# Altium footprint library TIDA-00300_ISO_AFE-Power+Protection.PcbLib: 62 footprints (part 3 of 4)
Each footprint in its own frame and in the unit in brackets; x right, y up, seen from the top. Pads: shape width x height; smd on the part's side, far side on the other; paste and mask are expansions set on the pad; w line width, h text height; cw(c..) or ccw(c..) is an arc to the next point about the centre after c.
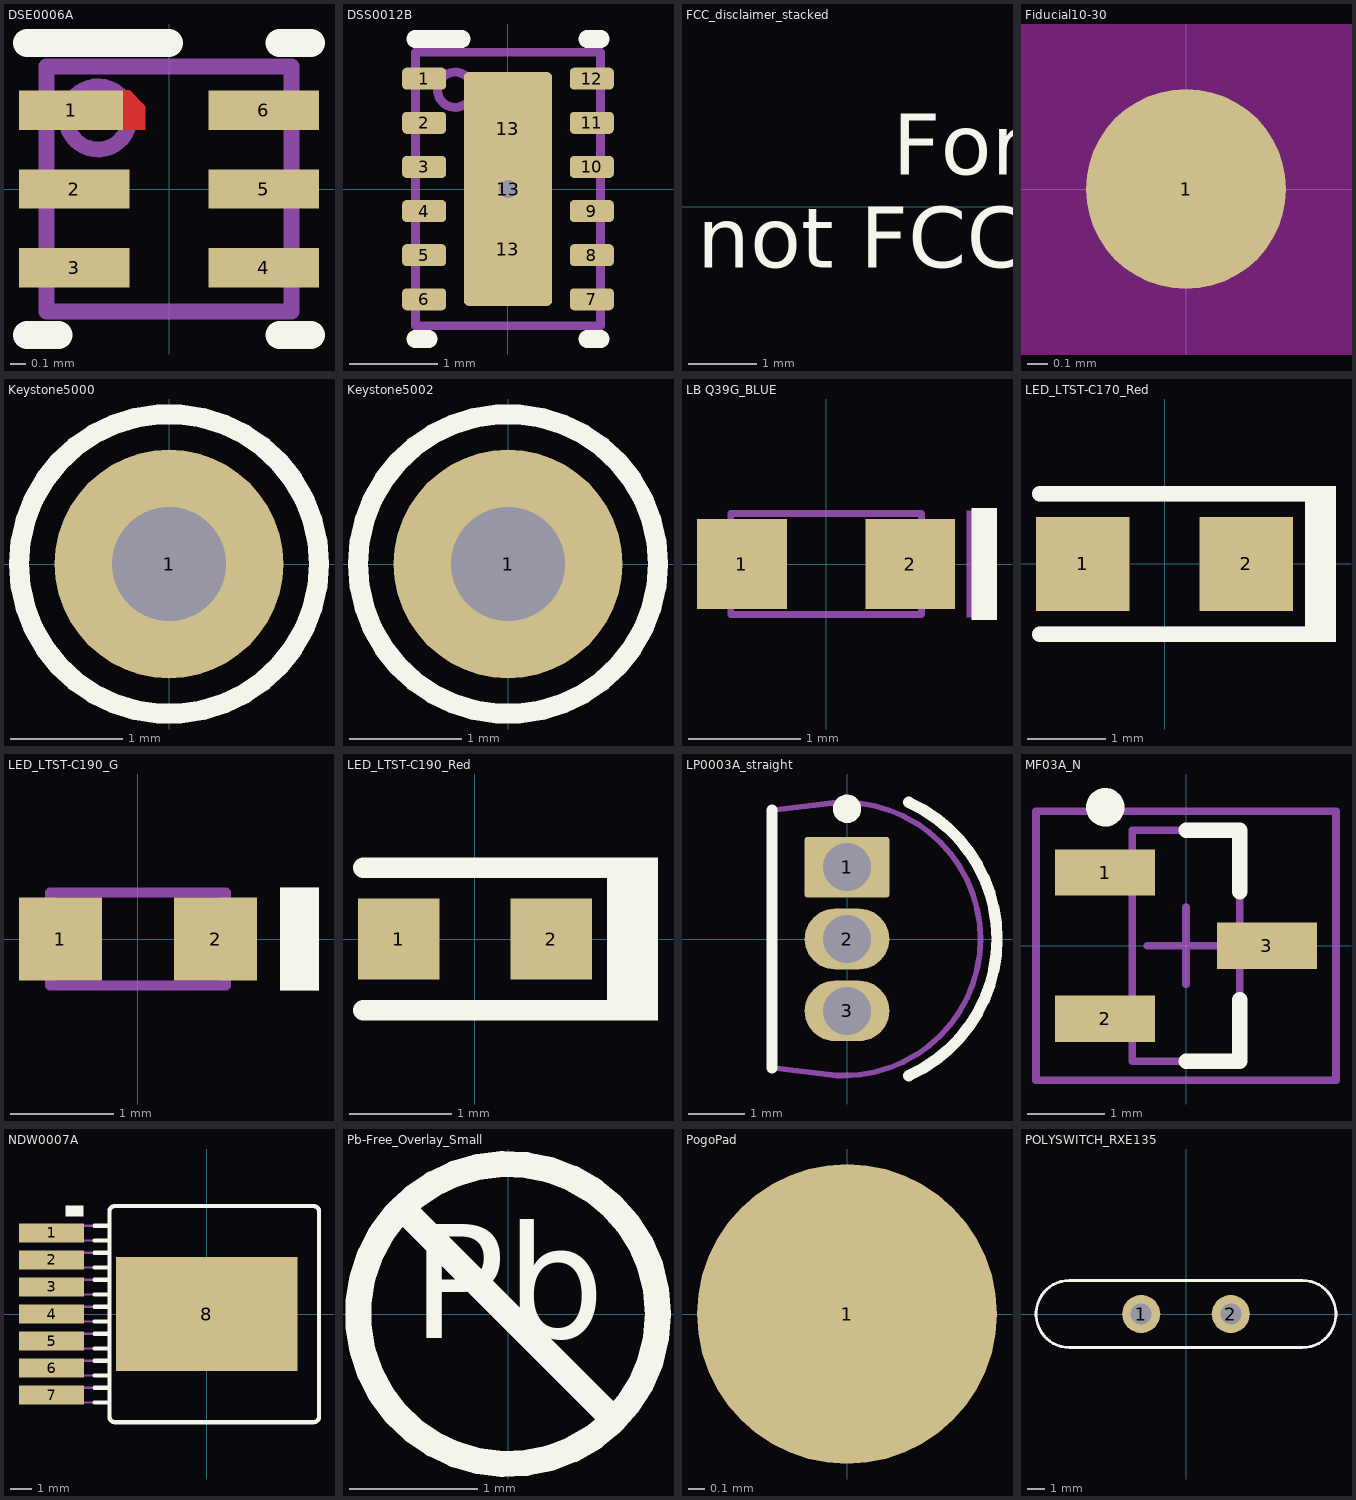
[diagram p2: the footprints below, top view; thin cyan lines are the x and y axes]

## DSE0006A [mm] "TI recommended land pattern"
height 0.8
pads (6):
  rect 0.66x0.25 smd: 1(-0.62,0.5)
  rect 0.7x0.25 smd: 2(-0.6,0) 3(-0.6,-0.5) 4(0.6,-0.5) 5(0.6,0) 6(0.6,0.5)
Top Layer:
  region: -0.3,0.625 -0.25,0.625 -0.15,0.525 -0.15,0.375 -0.3,0.375
Top Overlay:
  lines w0.178: -0.9,-0.925 -0.7,-0.925 ; -0.9,0.925 0,0.925 ; 0.7,-0.925 0.9,-0.925 ; 0.7,0.925 0.9,0.925
Mechanical 5:
  circle w0.1: c-0.45,0.45 r0.2
  lines w0.1: -0.775,-0.775 -0.775,0.775 0.775,0.775 0.775,-0.775 -0.775,-0.775
  text ".Designator" at 0.898,0.652 h0.51
3D body: height 0.8, standoff 0, extent -0.774,-0.774 0.774,0.774
3D body: height 0.8, standoff 0.76, extent -0.548,0.362 -0.352,0.558

## DSS0012B [mm] "SON, 12-Leads, Body 2x3mm, Pitch 0.5mm, Thermal Pad 2.65x1.0mm, TI Recommended"
height 0.8
pads (15):
  rrect40% 0.5x0.25 smd: 1(-0.95,1.25) 2(-0.95,0.75) 3(-0.95,0.25) 4(-0.95,-0.25) 5(-0.95,-0.75) 6(-0.95,-1.25) 7(0.95,-1.25) 8(0.95,-0.75) 9(0.95,-0.25) 10(0.95,0.25) 11(0.95,0.75) 12(0.95,1.25)
  rrect50% 0.949x1.168 on Top Paste: 13(0,-0.684) 13(0,0.684)
  rrect11% 1x2.65 smd paste-0.5: 13(0,0)
via 0,0 diameter 0.5 hole 0.2
Top Overlay:
  lines w0.2: -1.05,-1.7 -0.9,-1.7 ; -1.05,1.7 -0.525,1.7 ; 0.9,-1.7 1.05,-1.7 ; 0.9,1.7 1.05,1.7
Mechanical 5:
  circle w0.1: c-0.6,1.125 r0.2
  lines w0.1: -1.05,-1.55 1.05,-1.55 1.05,1.55 -1.05,1.55 -1.05,-1.55
  text ".Designator" at -0.25,0.728 h0.51
3D body "DSS0012A.stp": height 0.8, standoff 0, extent -1,-1.5 1,1.5
3D body: height 0.81, standoff 0.5, extent -0.799,0.926 -0.401,1.324

## FCC_disclaimer_stacked [mm]
Top Overlay:
  text "For evaluation only;" at -5.834,0.178 h1.52
  text "not FCC approved for resale." at -8.688,-1.178 h1.52

## Fiducial10-30 [mm]
pads (1):
  round 1 smd mask+1: 1(0,0)
Top Layer keep-out:
  circle w1.678: c0,0 r0.75

## Keystone5000 [mil] "For Keystone 500x miniature loop terminals"
height 181.1
pads (1):
  round 80 hole 40: 1(0,0)
Top Overlay:
  circle w7: c0,0 r52.5
Mechanical 5:
  circle w3.94: c0,0 r52.5
  text ".Designator" at -92.97,-15 h20
3D body "Keystone_5000.stp": height 181.97, standoff -118.11, extent -49,-49 49.04,49.24

## Keystone5002 [mil] "For Keystone 500x miniature loop terminals"
height 181.1
pads (1):
  round 80 hole 40: 1(0,0)
Top Overlay:
  circle w7: c0,0 r52.5
Mechanical 5:
  circle w3.94: c0,0 r52.5
  text ".Designator" at -19,98 h20
3D body "Keystone_5002.stp": height 181.97, standoff -118.11, extent -49,-49 49.04,49.23

## LB Q39G_BLUE [mm] "OSRAM"
height 0.4
pads (2):
  rect 0.8x0.8 smd: 1(-0.75,0) 2(0.75,0)
Top Overlay:
  rectangle: 1.298,-0.5 1.523,0.5
Mechanical 5:
  circle w0.05: c0.65,0.25 r0.1
  rectangle: 1.25,-0.475 1.45,0.475
  lines w0.06: -0.85,-0.45 -0.85,0.45 ; -0.85,-0.45 0.85,-0.45 ; -0.85,-0.45 -0.85,0.45 ; -0.85,-0.45 0.85,-0.45 ; -0.85,0.45 0.85,0.45 ; -0.85,0.45 0.85,0.45 ; 0.85,-0.45 0.85,0.45 ; 0.85,-0.45 0.85,0.45
  text ".Designator" at -0.65,-0.35 h0.51
3D body: height 0.15, standoff 0, extent 0.576,-0.449 0.849,0.449
3D body: height 0.4, standoff 0.15, extent -0.574,-0.449 0.574,0.449
3D body: height 0.15, standoff 0, extent -0.574,-0.449 0.574,0.449
3D body: height 0.15, standoff 0, extent -0.849,-0.449 -0.576,0.449

## LED_LTST-C170_Red [mm] "LITE-ON"
height 1.1
pads (2):
  rect 1.2x1.2 smd: 1(-1.05,0) 2(1.05,0)
Top Overlay:
  rectangle: 1.8,-1 2.2,1
  lines w0.2: -1.6,-0.9 2.1,-0.9 ; -1.6,0.9 2.1,0.9
Mechanical 5:
  rectangle: 1.8,-1 2.2,1
  lines w0.2: -1.6,-0.9 2.1,-0.9 ; -1.6,0.9 2.1,0.9
  text ".Designator" at -0.457,-0.279 h0.51
3D body: height 1.1, standoff 0.5, extent -0.699,-0.624 0.699,0.624
3D body: height 0.5, standoff 0, extent -1.05,-0.675 1.05,0.675

## LED_LTST-C190_G [mm] "Lite-On"
height 0.9
pads (2):
  rect 0.8x0.8 smd: 1(-0.75,0) 2(0.75,0)
Top Overlay:
  rectangle: 1.375,-0.5 1.75,0.5
Mechanical 5:
  rectangle: 1.375,-0.5 1.75,0.5
  lines w0.1: -0.85,-0.45 0.85,-0.45 0.85,0.45 -0.85,0.45 -0.85,-0.45
  text ".Designator" at 0.326,0.298 h0.51
3D body: height 0.36, standoff 0.35, extent -0.849,-0.449 -0.501,0.449
3D body: height 0.9, standoff 0.35, extent -0.499,-0.449 0.499,0.449
3D body: height 0.35, standoff 0, extent -0.849,-0.449 0.849,0.449
3D body: height 0.36, standoff 0.35, extent 0.501,-0.449 0.849,0.449

## LED_LTST-C190_Red [mm] "Lite-On"
height 0.9
pads (2):
  rect 0.8x0.8 smd: 1(-0.75,0) 2(0.75,0)
Top Overlay:
  region: 1.8,0.8 1.3,0.8 1.3,-0.8 1.8,-0.8
  lines w0.2: -1.1,-0.7 1.4,-0.7 ; -1.1,0.7 1.4,0.7
Mechanical 5:
  region: 1.8,0.75 1.3,0.75 1.3,-0.75 1.8,-0.75
  lines w0.1: -1.1,-0.7 1.4,-0.7 ; -1.1,0.7 1.4,0.7
  text ".Designator" at 0.885,0.374 h0.51
3D body "Lite-On_LTST_C190_red.stp": height 0.9, standoff 0, extent -0.85,-0.45 0.85,0.45

## LP0003A_straight [mm] "TH, 3-Leads, Pin Spacing 1.27mm"
height 6.84
pads (3):
  rrect9% 1.5x1.07 hole 0.85: 1(0,1.27)
  rrect100% 1.5x1.07 hole 0.85: 2(0,0) 3(0,-1.27)
Top Overlay:
  circle w0.25: c0,2.3 r0.125
  lines w0.2: -1.325,-2.273 -1.325,2.273 ; 1.092,-2.415 ccw(c0,0) 1.092,2.415
Mechanical 5:
  lines w0.1: -1.325,-2.273 -0.185,-2.413 -0.055,-2.413 ccw(c-0.055,0) -0.055,2.412 -0.185,2.412 -1.325,2.273 -1.325,-2.273
  text ".Designator" at 4.47,-0.254 h0.51
3D body "LP0003A.stp": height 6.84, standoff -10.69, extent -1.337,-2.413 2.345,2.412

## MF03A_N [mm] "SOT23, 3-Leads, Body 2.9x1.3mm, Pitch 0.95mm, Lead Span 2.4mm, IPC Medium Density"
height 1.12
pads (3):
  rect 1.3x0.6 smd: 1(-1.05,0.95) 2(-1.05,-0.95) 3(1.05,0)
Top Overlay:
  circle w0.25: c-1.05,1.8 r0.125
  lines w0.2: 0,-1.5 0.7,-1.5 0.7,-0.7 ; 0,1.5 0.7,1.5 0.7,0.7
Mechanical 5:
  text ".Designator" at -0.055,-0.109 h0.51
Mechanical 13:
  lines w0.1: -0.7,-1.5 -0.7,1.5 0.7,1.5 0.7,-1.5 -0.7,-1.5
Mechanical 15:
  lines w0.1: -0.5,0 0.5,0 ; 0,-0.5 0,0.5 ; -1.95,-1.75 -1.95,1.75 1.95,1.75 1.95,-1.75 -1.95,-1.75
3D body: height 1.12, standoff 0, extent -0.7,-1.5 0.7,1.5

## NDW0007A [mm] "TI Recommended"
height 4.67
pads (8):
  rect 3.06x0.89 smd: 1(-7.305,3.81) 2(-7.305,2.54) 3(-7.305,1.27) 4(-7.305,0) 5(-7.305,-1.27) 6(-7.305,-2.54) 7(-7.305,-3.81)
  rect 8.54x5.35 smd: 8(0,0)
Top Overlay:
  region: -6.65,5.1 -6.65,4.575 -5.8,4.575 -5.8,5.1
  lines w0.2: -5.28,-4.16 -4.58,-4.16 -4.58,-3.47 -5.28,-3.47 ; -5.28,-2.89 -4.58,-2.89 -4.58,-2.2 -5.28,-2.2 ; -5.28,-1.62 -4.58,-1.62 -4.58,-0.93 -5.28,-0.93 ; -5.28,-0.35 -4.58,-0.35 -4.58,0.34 -5.28,0.34 ; -5.28,0.92 -4.58,0.92 -4.58,1.61 -5.28,1.61 ; -5.28,2.19 -4.58,2.19 -4.58,2.88 -5.28,2.88 ; -5.28,3.46 -4.58,3.46 -4.58,4.15 -5.28,4.15 ; -4.58,-4.837 ccw(c-4.33,-4.835) -4.332,-5.085 -4.33,-5.085 5.02,-5.085 5.022,-5.085 ccw(c5.02,-4.835) 5.27,-4.837 5.27,-4.835 5.27,4.825 5.27,4.827 ccw(c5.02,4.825) 5.022,5.075 5.02,5.075 -4.33,5.075 -4.332,5.075 ccw(c-4.33,4.825) -4.58,4.827 -4.58,4.825 -4.58,-4.835 -4.58,-4.837
Mechanical 5:
  lines w0.1: -4.332,-5.085 cw(c-4.33,-4.835) -4.58,-4.837 -4.58,-4.835 -4.58,4.825 -4.58,4.827 cw(c-4.33,4.825) -4.332,5.075 ; -4.33,-5.085 5.02,-5.085 ; -4.33,5.075 5.02,5.075 ; 5.022,-5.085 ccw(c5.02,-4.835) 5.27,-4.837 ; 5.022,5.075 cw(c5.02,4.825) 5.27,4.827 ; 5.27,-4.835 5.27,4.825 ; -8.5,-4.16 -5.28,-4.16 -4.58,-4.16 -4.58,-3.47 -5.28,-3.47 -8.5,-3.47 -8.5,-4.16 ; -8.5,-2.89 -5.28,-2.89 -4.58,-2.89 -4.58,-2.2 -5.28,-2.2 -8.5,-2.2 -8.5,-2.89 ; -8.5,-1.62 -5.28,-1.62 -4.58,-1.62 -4.58,-0.93 -5.28,-0.93 -8.5,-0.93 -8.5,-1.62 ; -8.5,-0.35 -5.28,-0.35 -4.58,-0.35 -4.58,0.34 -5.28,0.34 -8.5,0.34 -8.5,-0.35 ; -8.5,0.92 -5.28,0.92 -4.58,0.92 -4.58,1.61 -5.28,1.61 -8.5,1.61 -8.5,0.92 ; -8.5,2.19 -5.28,2.19 -4.58,2.19 -4.58,2.88 -5.28,2.88 -8.5,2.88 -8.5,2.19 ; -8.5,3.46 -5.28,3.46 -4.58,3.46 -4.58,4.15 -5.28,4.15 -8.5,4.15 -8.5,3.46
  text ".Designator" at -1.725,-0.45 h0.51
3D body "NDW0007A.stp": height 4.78, standoff 0.01, extent -8.495,-5.08 5.275,5.08

## Pb-Free_Overlay_Small [mm]
Top Overlay:
  circle w0.203: c0,0 r1.168
  lines w0.203: -0.826,0.826 0.826,-0.826
  text "Pb" at -0.752,-0.48 h1.52

## PogoPad [mil] "No Solder Paste"
pads (1):
  round 70 smd paste-35: 1(0,0)

## POLYSWITCH_RXE135 [mil]
height 40
pads (2):
  round 85 hole 47: 1(-100,0) 2(100,0)
Top Overlay:
  lines w6: -260,-75 cw(c-260,0) -260,75 260,75 cw(c260,0) 260,-75 -260,-75
Mechanical 5:
  lines w6: -260,-75 cw(c-260,0) -260,75 260,75 cw(c260,0) 260,-75 -260,-75
  text ".Designator" at -1.14,7.68 h20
